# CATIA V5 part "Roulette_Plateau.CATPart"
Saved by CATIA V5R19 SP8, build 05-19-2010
Part number: Roulette_Plateau
Nomenclature: 55
Material "Caoutchouc": density 910 kg/m3, Young's modulus 2e+06 Pa, Poisson ratio 0.49, thermal expansion 0.000162 1/K
Bounding box of the stored display mesh (mm): x -27.494 to 27.494, y -27.5 to 27.5, z -11.5 to 11.5
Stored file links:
  C:\Users\rphgr\Desktop\0_Tapis_TC520B_vitesse\Roulette_Plateau.CATPart
  D:\Programmes\DassaultSysteme\win_b64\startup\materials\French\Catalog.CATMaterial
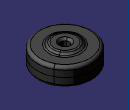
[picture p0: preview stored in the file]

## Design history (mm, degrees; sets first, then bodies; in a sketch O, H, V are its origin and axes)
AxisSystem1: origin (0, 0, 0), X (1, 0, 0), Y (0, 1, 0), Z (0, 0, 1)
Body1 (main body), material "Caoutchouc"
  Sketch1 on ZX plane of AxisSystem1, origin (0, 0, 0), H (0, 0, 1), V (1, 0, 0)
    axis line L1 (-163.7526, 0) -> (330.9073, 0)
    point P1 (-163.7526, 0)
    point P3 (0, 4.125)
    line L2 (0, 4.125) -> (-11.5, 4.125)
    point P4 (-11.5, 4.125)
    line L3 (-11.5, 4.125) -> (-11.5, 11.5)
    point P5 (-11.5, 11.5)
    line L4 (-11.5, 11.5) -> (-9.25, 15)
    point P6 (-9.25, 15)
    line L5 (-9.25, 15) -> (-9.25, 27.5)
    point P7 (-9.25, 27.5)
    line L6 (-9.25, 27.5) -> (0, 27.5)
    point P8 (0, 27.5)
    point P9 (0, 4.125)
    point P10 (11.5, 4.125)
    point P11 (11.5, 11.5)
    point P12 (9.25, 15)
    point P13 (9.25, 27.5)
    point P14 (0, 27.5)
    line L7 (0, 4.125) -> (11.5, 4.125)
    line L8 (11.5, 4.125) -> (11.5, 11.5)
    line L9 (11.5, 11.5) -> (9.25, 15)
    line L10 (9.25, 15) -> (9.25, 27.5)
    line L11 (9.25, 27.5) -> (0, 27.5)
    "Radius" L2 L1 = 4.125
    distance L3 V = 11.5
    "Radius" P5 L1 = 11.5
    distance L5 V = 9.25
    "Radius" L6 L1 = 27.5
    "Radius" P6 L1 = 15
    coincidence: P1 H, P3 V, P8 V, P3 P9, P8 P14
    horizontal: L1 H, L2 H, L6 H
    vertical: L3 V, L5 V
    symmetry: P3 P9 V, P4 P10 V, P5 P11 V, P6 P12 V, P7 P13 V, P8 P14 V, L2 L7 V, L3 L8 V, L4 L9 V, L5 L10 V, L6 L11 V
  Shaft1: profile Sketch1, axis Sketch1.L1, angle 360
  Fillet1: radius 3, on edge [face of Shaft1 from Sketch1.L11 | face of Shaft1 from Sketch1.L10]; face of Shaft1 from Sketch1.L10; edge [face of Shaft1 from Sketch1.L9 | face of Shaft1 from Sketch1.L8]; edge [face of Shaft1 from Sketch1.L5 | face of Shaft1 from Sketch1.L6]; edge [face of Shaft1 from Sketch1.L4 | face of Shaft1 from Sketch1.L5]; edge [face of Shaft1 from Sketch1.L3 | face of Shaft1 from Sketch1.L4]
  Chamfer1: length 2, angle 45, on edge [face of Shaft1 from Sketch1.L2 | face of Shaft1 from Sketch1.L3]; edge [face of Shaft1 from Sketch1.L8 | face of Shaft1 from Sketch1.L7]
